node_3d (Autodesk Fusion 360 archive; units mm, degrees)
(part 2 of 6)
sketch "mountbottom" plane through (0, 0, -26) normal (0, 0, 1) x axis (-1, 0, 0)
  line L1 (-3.25, -49) -> (-15, -49)
  line L2 (-3.25, -50.9) -> (-3.25, -49)
  line L3 (3.25, -50.9) -> (-3.25, -50.9)
  line L4 (3.25, -49) -> (3.25, -50.9)
  line L5 (15, -49) -> (3.25, -49)
  line L6 (15, -47) -> (15, -49)
  line L7 (46, -47) -> (15, -47)
  line L8 (47, 46) -> (47, -46)
  line L9 (-46, 47) -> (46, 47)
  line L10 (-47, -46) -> (-47, 46)
  line L11 (-15, -47) -> (-46, -47)
  line L12 (-15, -49) -> (-15, -47)
  line L13 (-15.575, -12.63) -> (-15.575, 11.37)
  line L14 (12.425, -16.63) -> (-11.575, -16.63)
  line L15 (16.425, 11.37) -> (16.425, -12.63)
  line L16 (-11.575, 15.37) -> (12.425, 15.37)
  line L17 (4.235, 0.64) -> (-3.385, 0.64)
  line L18 (4.235, -1.9) -> (4.235, 0.64)
  line L19 (-3.385, -1.9) -> (4.235, -1.9)
  line L20 (-3.385, 0.64) -> (-3.385, -1.9)
  line L21 (-2.715, -0.03) -> (-1.515, -0.03)
  line L22 (-2.715, -1.23) -> (-2.715, -0.03)
  line L23 (-1.515, -1.23) -> (-2.715, -1.23)
  line L24 (-1.515, -0.03) -> (-1.515, -1.23)
  line L25 (-0.175, -0.03) -> (1.025, -0.03)
  line L26 (-0.175, -1.23) -> (-0.175, -0.03)
  line L27 (1.025, -1.23) -> (-0.175, -1.23)
  line L28 (1.025, -0.03) -> (1.025, -1.23)
  line L29 (2.365, -0.03) -> (3.565, -0.03)
  line L30 (2.365, -1.23) -> (2.365, -0.03)
  line L31 (3.565, -1.23) -> (2.365, -1.23)
  line L32 (3.565, -0.03) -> (3.565, -1.23)
  line L33 (4.035, 1.44) -> (-3.185, 1.44)
  line L34 (5.035, -1.7) -> (5.035, 0.44)
  line L35 (-3.185, -2.7) -> (4.035, -2.7)
  line L36 (-4.185, 0.44) -> (-4.185, -1.7)
  line L37 (8.425, 7.37) -> (16.425, 15.37)
  line L38 (16.425, 7.37) -> (8.425, 15.37)
  line L39 (11.375, 14.92) -> (13.475, 14.92)
  line L40 (8.875, 10.32) -> (8.875, 12.42)
  line L41 (13.475, 7.82) -> (11.375, 7.82)
  line L42 (15.975, 12.42) -> (15.975, 10.32)
  line L43 (8.875, 7.82) -> (15.975, 14.92)
  line L44 (15.975, 7.82) -> (8.875, 14.92)
  line L45 (-10.525, 7.82) -> (-12.625, 7.82)
  line L46 (-8.025, 12.42) -> (-8.025, 10.32)
  line L47 (-12.625, 14.92) -> (-10.525, 14.92)
  line L48 (-15.125, 10.32) -> (-15.125, 12.42)
  line L49 (-8.025, 14.92) -> (-15.125, 7.82)
  line L50 (-15.125, 14.92) -> (-8.025, 7.82)
  line L51 (11.375, -9.08) -> (13.475, -9.08)
  line L52 (8.875, -13.68) -> (8.875, -11.58)
  line L53 (13.475, -16.18) -> (11.375, -16.18)
  line L54 (15.975, -11.58) -> (15.975, -13.68)
  line L55 (8.875, -16.18) -> (15.975, -9.08)
  line L56 (15.975, -16.18) -> (8.875, -9.08)
  line L57 (-12.625, -9.08) -> (-10.525, -9.08)
  line L58 (-15.125, -13.68) -> (-15.125, -11.58)
  line L59 (-10.525, -16.18) -> (-12.625, -16.18)
  line L60 (-8.025, -11.58) -> (-8.025, -13.68)
  line L61 (-15.125, -16.18) -> (-8.025, -9.08)
  line L62 (-8.025, -16.18) -> (-15.125, -9.08)
  arc A1 centre (46, -46) radius 1 clockwise from (47, -46) to (46, -47)
  arc A2 centre (46, 46) radius 1 clockwise from (46, 47) to (47, 46)
  arc A3 centre (-46, 46) radius 1 clockwise from (-47, 46) to (-46, 47)
  arc A4 centre (-46, -46) radius 1 clockwise from (-46, -47) to (-47, -46)
  arc A5 centre (-11.575, 11.37) radius 4 clockwise from (-15.575, 11.37) to (-11.575, 15.37)
  arc A6 centre (-11.575, -12.63) radius 4 clockwise from (-11.575, -16.63) to (-15.575, -12.63)
  arc A7 centre (12.425, -12.63) radius 4 clockwise from (16.425, -12.63) to (12.425, -16.63)
  arc A8 centre (12.425, 11.37) radius 4 clockwise from (12.425, 15.37) to (16.425, 11.37)
  circle C1 centre (12.425, -12.63) radius 1.55
  circle C2 centre (-11.575, -12.63) radius 1.55
  circle C3 centre (12.425, 11.37) radius 1.55
  circle C4 centre (-11.575, 11.37) radius 1.55
  circle C5 centre (16.68, 32.54) radius 4.65
  circle C6 centre (-16.34, 32.54) radius 1.65
  circle C7 centre (-16.34, 32.54) radius 1.65
  circle C8 centre (-16.34, 32.54) radius 4.65
  circle C9 centre (-16.34, 32.54) radius 4.65
  circle C10 centre (16.68, -32.865) radius 4.65
  circle C11 centre (16.68, -32.865) radius 1.65
  circle C12 centre (-16.33, -33.5) radius 4.65
  circle C13 centre (-16.33, -33.5) radius 1.65
  circle C14 centre (12.425, -12.63) radius 3.55
  circle C15 centre (-11.575, -12.63) radius 3.55
  circle C16 centre (-11.575, 11.37) radius 3.55
  circle C17 centre (12.425, 11.37) radius 3.55
  arc A9 centre (4.035, -1.7) radius 1 clockwise from (5.035, -1.7) to (4.035, -2.7)
  arc A10 centre (4.035, 0.44) radius 1 clockwise from (4.035, 1.44) to (5.035, 0.44)
  arc A11 centre (-3.185, 0.44) radius 1 clockwise from (-4.185, 0.44) to (-3.185, 1.44)
  arc A12 centre (-3.185, -1.7) radius 1 clockwise from (-3.185, -2.7) to (-4.185, -1.7)
  arc A13 centre (13.475, 12.42) radius 2.5 clockwise from (13.475, 14.92) to (15.975, 12.42)
  arc A14 centre (11.375, 12.42) radius 2.5 clockwise from (8.875, 12.42) to (11.375, 14.92)
  arc A15 centre (13.475, 10.32) radius 2.5 clockwise from (15.975, 10.32) to (13.475, 7.82)
  arc A16 centre (11.375, 10.32) radius 2.5 clockwise from (11.375, 7.82) to (8.875, 10.32)
  arc A17 centre (-12.625, 12.42) radius 2.5 clockwise from (-15.125, 12.42) to (-12.625, 14.92)
  arc A18 centre (-10.525, 12.42) radius 2.5 clockwise from (-10.525, 14.92) to (-8.025, 12.42)
  arc A19 centre (-10.525, 10.32) radius 2.5 clockwise from (-8.025, 10.32) to (-10.525, 7.82)
  arc A20 centre (-12.625, 10.32) radius 2.5 clockwise from (-12.625, 7.82) to (-15.125, 10.32)
  arc A21 centre (13.475, -13.68) radius 2.5 clockwise from (15.975, -13.68) to (13.475, -16.18)
  arc A22 centre (11.375, -13.68) radius 2.5 clockwise from (11.375, -16.18) to (8.875, -13.68)
  arc A23 centre (11.375, -11.58) radius 2.5 clockwise from (8.875, -11.58) to (11.375, -9.08)
  arc A24 centre (13.475, -11.58) radius 2.5 clockwise from (13.475, -9.08) to (15.975, -11.58)
  arc A25 centre (-12.625, -13.68) radius 2.5 clockwise from (-12.625, -16.18) to (-15.125, -13.68)
  arc A26 centre (-12.625, -11.58) radius 2.5 clockwise from (-15.125, -11.58) to (-12.625, -9.08)
  arc A27 centre (-10.525, -11.58) radius 2.5 clockwise from (-10.525, -9.08) to (-8.025, -11.58)
  arc A28 centre (-10.525, -13.68) radius 2.5 clockwise from (-8.025, -13.68) to (-10.525, -16.18)
  point P82 (12.425, 11.37)
  point P33 (12.425, 11.37)
  point P87 (12.425, 11.37)
  point P36 (12.425, 11.37)
  point P83 (15.975, 14.92)
  point P84 (8.875, 14.92)
  point P86 (15.975, 7.82)
  point P85 (8.875, 7.82)
  point P104 (-11.575, 11.37)
  point P37 (-11.575, 11.37)
  point P103 (-15.125, 14.92)
  point P102 (-8.025, 14.92)
  point P101 (-8.025, 7.82)
  point P100 (-15.125, 7.82)
  point P121 (12.425, -12.63)
  point P30 (12.425, -12.63)
  point P120 (15.975, -16.18)
  point P119 (8.875, -16.18)
  point P118 (8.875, -9.08)
  point P117 (15.975, -9.08)
  point P138 (-11.575, -12.63)
  point P35 (-11.575, -12.63)
  point P136 (-15.125, -16.18)
  point P135 (-15.125, -9.08)
  point P134 (-8.025, -9.08)
  point P137 (-8.025, -16.18)
  tangent L35 A9
  tangent L34 A9
  tangent L33 A10
  tangent L34 A10
  equal A9 A10
  tangent L33 A11
  tangent L36 A11
  equal A9 A11
  tangent L35 A12
  tangent L36 A12
  equal A9 A12
  coincident L37 P82
  coincident L38 P82
  coincident P33 P82
  horizontal L39
  perpendicular L39 L40
  parallel L39 L41
  parallel L40 L42
  coincident L43 P87
  coincident L44 P87
  coincident P36 P87
  coincident P83 L42
  coincident P83 L39
  tangent L42 A13
  tangent L39 A13
  coincident P84 L39
  coincident P84 L40
  tangent L39 A14
  tangent L40 A14
  equal A13 A14
  coincident P86 L41
  coincident P86 L42
  tangent L41 A15
  tangent L42 A15
  equal A13 A15
  coincident P85 L41
  coincident P85 L40
  tangent L41 A16
  tangent L40 A16
  equal A13 A16
  horizontal L45
  perpendicular L45 L46
  parallel L45 L47
  parallel L46 L48
  coincident L49 P104
  coincident L50 P104
  coincident P37 P104
  coincident P103 L47
  coincident P103 L48
  tangent L47 A17
  tangent L48 A17
  coincident P102 L47
  coincident P102 L46
  tangent L47 A18
  tangent L46 A18
  equal A17 A18
  coincident P101 L46
  coincident P101 L45
  tangent L46 A19
  tangent L45 A19
  equal A17 A19
  coincident P100 L45
  coincident P100 L48
  tangent L45 A20
  tangent L48 A20
  equal A17 A20
  horizontal L51
  perpendicular L51 L52
  parallel L51 L53
  parallel L52 L54
  coincident L55 P121
  coincident L56 P121
  coincident P30 P121
  coincident P120 L53
  coincident P120 L54
  tangent L53 A21
  tangent L54 A21
  coincident P119 L53
  coincident P119 L52
  tangent L53 A22
  tangent L52 A22
  equal A21 A22
  coincident P118 L52
  coincident P118 L51
  tangent L52 A23
  tangent L51 A23
  equal A21 A23
  coincident P117 L51
  coincident P117 L54
  tangent L51 A24
  tangent L54 A24
  equal A21 A24
  horizontal L57
  perpendicular L57 L58
  parallel L57 L59
  parallel L58 L60
  coincident L61 P138
  coincident L62 P138
  coincident P35 P138
  coincident P136 L59
  coincident P136 L58
  tangent L59 A25
  tangent L58 A25
  coincident P135 L58
  coincident P135 L57
  tangent L58 A26
  tangent L57 A26
  equal A25 A26
  coincident P134 L57
  coincident P134 L60
  tangent L57 A27
  tangent L60 A27
  equal A25 A27
  coincident P137 L60
  coincident P137 L59
  tangent L60 A28
  tangent L59 A28
  equal A25 A28
  dimension "d179" = 2
  dimension "d180" = 2
  dimension "d181" = 2
  dimension "d182" = 2
  dimension "d186" radius A9 = 1
  dimension "d331" distance P85 P86 = 7.1
  dimension "d332" distance P84 P85 = 7.1
  dimension "d333" radius A13 = 2.5
  dimension "d336" distance P102 P103 = 7.1
  dimension "d337" distance P101 P102 = 7.1
  dimension "d338" radius A17 = 2.5
  dimension "d339" distance P119 P120 = 7.1
  dimension "d340" distance P118 P119 = 7.1
  dimension "d341" radius A21 = 2.5
  dimension "d342" distance P136 P137 = 7.1
  dimension "d343" distance P135 P136 = 7.1
  dimension "d344" radius A25 = 2.5
extrude "Extrude25" new body sketch "mountbottom" profile of C1 C2 C3 C4 C14 C15 C16 C17 to an object bodies "dwnmount4", "dwnmount2", "dwnmount1", "dwnmount4 (1)"
extrude "Extrude26" cut sketch "mountbottom" profile of L17 L18 L19 L20 L21 L22 L23 L24 L25 L26 L27 L28 L29 L30 L31 L32 L34 L33 L35 L36 A9 A10 A11 A12 against normal blind 9
offset_faces "OffsetFaces12" distance 0.2
offset_faces "OffsetFaces13" distance 0.2
move "Move1" TranslateX 0 TranslateY 0 TranslateZ 0.2
sketch "Sketch16" plane through (0, 0, -5.4) normal (0, 0, 1) x axis (-1, 0, 0)
  line L1 (51.5, 45) -> (51.5, -45)
  line L2 (-47.5, 49) -> (47.5, 49)
  line L3 (-51.5, -45) -> (-51.5, 45)
  line L4 (47.5, -49) -> (-47.5, -49)
  line L5 (-14.78, -33.5) -> (-16.33, -33.5)
  line L6 (-21, -32.865) -> (16.68, -32.865)
  line L7 (-16.34, 32.54) -> (16.68, 32.54)
  line L8 (-12.83, -29.5) -> (-19.83, -37.5)
  line L9 (-19.83, -29.5) -> (-12.83, -37.5)
  line L10 (-16, -20) -> (-16, -48)
  line L11 (-18, -48) -> (-18, -20)
  line L12 (-16, -32.865) -> (-18, -32.865)
  line L13 (-20.5, -28.865) -> (-13.5, -36.865)
  line L14 (-13.5, -28.865) -> (-20.5, -36.865)
  line L15 (-16.8856, -34.6) -> (-16.8856, -32.865)
  line L16 (-20.3856, -36.865) -> (-13.3856, -28.865)
  line L17 (-13.3856, -36.865) -> (-20.3856, -28.865)
  line L18 (-18.3856, -36.865) -> (-15.3856, -36.865)
  line L19 (-20.3856, -30.865) -> (-20.3856, -34.865)
  line L20 (-15.3856, -28.865) -> (-18.3856, -28.865)
  line L21 (-13.3856, -34.865) -> (-13.3856, -30.865)
  line L22 (-20.3856, -28.865) -> (-13.3856, -36.865)
  line L23 (-13.3856, -28.865) -> (-20.3856, -36.865)
  line L24 (-18, 20) -> (-18, 48)
  line L25 (-16, 48) -> (-16, 20)
  line L26 (16, 20) -> (16, 48)
  line L27 (18, 48) -> (18, 20)
  line L28 (18, -20) -> (18, -48)
  line L29 (16, -48) -> (16, -20)
  line L30 (18, -32.865) -> (16, -32.865)
  line L31 (17, -34.3816) -> (17, -32.865)
  line L32 (13.18, -32.865) -> (20.18, -32.865)
  line L33 (15.5, -36.865) -> (18.5, -36.865)
  line L34 (13.5, -30.865) -> (13.5, -34.865)
  line L35 (18.5, -28.865) -> (15.5, -28.865)
  line L36 (20.5, -34.865) -> (20.5, -30.865)
  line L37 (13.5, -28.865) -> (20.5, -36.865)
  line L38 (20.5, -28.865) -> (13.5, -36.865)
  line L39 (-18, 32.54) -> (-16, 32.54)
  line L40 (-17, 30.5) -> (-17, 32.54)
  line L41 (-18.5, 28.54) -> (-15.5, 28.54)
  line L42 (-20.5, 34.54) -> (-20.5, 30.54)
  line L43 (-15.5, 36.54) -> (-18.5, 36.54)
  line L44 (-13.5, 30.54) -> (-13.5, 34.54)
  line L45 (-20.5, 36.54) -> (-13.5, 28.54)
  line L46 (-13.5, 36.54) -> (-20.5, 28.54)
  line L47 (18, 32.54) -> (16, 32.54)
  line L48 (17, 28) -> (17, 32.54)
  line L49 (15.5, 28.54) -> (18.5, 28.54)
  line L50 (13.5, 34.54) -> (13.5, 30.54)
  line L51 (18.5, 36.54) -> (15.5, 36.54)
  line L52 (20.5, 30.54) -> (20.5, 34.54)
  line L53 (13.5, 36.54) -> (20.5, 28.54)
  line L54 (20.5, 36.54) -> (13.5, 28.54)
  arc A1 centre (47.5, -45) radius 4 clockwise from (51.5, -45) to (47.5, -49)
  arc A2 centre (47.5, 45) radius 4 clockwise from (47.5, 49) to (51.5, 45)
  arc A3 centre (-47.5, 45) radius 4 clockwise from (-51.5, 45) to (-47.5, 49)
  arc A4 centre (-47.5, -45) radius 4 clockwise from (-47.5, -49) to (-51.5, -45)
  circle C1 centre (-36.64, 35.04) radius 0.7747
  circle C2 centre (-30.29, 37.58) radius 0.7747
  circle C3 centre (-37.91, 32.5) radius 0.8763
  circle C4 centre (-32.83, 32.5) radius 2.0447
  circle C5 centre (-27.75, 32.5) radius 0.8763
  circle C6 centre (-16.34, 32.54) radius 1.55
  circle C7 centre (-3.64, 35.04) radius 0.7747
  circle C8 centre (-4.91, 32.5) radius 0.8763
  circle C9 centre (-36.64, 2.04) radius 0.7747
  circle C10 centre (-30.29, 4.58) radius 0.7747
  circle C11 centre (-3.64, 2.04) radius 0.7747
  circle C12 centre (2.71, 37.58) radius 0.7747
  circle C13 centre (0.17, 32.5) radius 2.0447
  circle C14 centre (5.25, 32.5) radius 0.8763
  circle C15 centre (16.68, 32.54) radius 1.55
  circle C16 centre (29.36, 35.04) radius 0.7747
  circle C17 centre (28.09, 32.5) radius 0.8763
  circle C18 centre (35.71, 37.58) radius 0.7747
  circle C19 centre (33.17, 32.5) radius 2.0447
  circle C20 centre (38.25, 32.5) radius 0.8763
  circle C21 centre (2.71, 4.58) radius 0.7747
  circle C22 centre (29.36, 2.04) radius 0.7747
  circle C23 centre (35.71, 4.58) radius 0.7747
  circle C24 centre (-37.91, -0.5) radius 0.8763
  circle C25 centre (-32.83, -0.5) radius 2.0447
  circle C26 centre (-27.75, -0.5) radius 0.8763
  circle C27 centre (-4.91, -0.5) radius 0.8763
  circle C28 centre (-30.29, -28.42) radius 0.7747
  circle C29 centre (-36.64, -30.96) radius 0.7747
  circle C30 centre (-37.91, -33.5) radius 0.8763
  circle C31 centre (-32.83, -33.5) radius 2.0447
  circle C32 centre (-27.75, -33.5) radius 0.8763
  circle C33 centre (-16.33, -33.5) radius 1.55
  circle C34 centre (-4.91, -33.5) radius 0.8763
  circle C35 centre (-3.64, -30.96) radius 0.7747
  circle C36 centre (0.17, -0.5) radius 2.0447
  circle C37 centre (5.25, -0.5) radius 0.8763
  circle C38 centre (28.09, -0.5) radius 0.8763
  circle C39 centre (33.17, -0.5) radius 2.0447
  circle C40 centre (38.25, -0.5) radius 0.8763
  circle C41 centre (2.71, -28.42) radius 0.7747
  circle C42 centre (0.17, -33.5) radius 2.0447
  circle C43 centre (5.25, -33.5) radius 0.8763
  circle C44 centre (16.68, -32.865) radius 1.55
  circle C45 centre (29.36, -30.96) radius 0.7747
  circle C46 centre (28.09, -33.5) radius 0.8763
  circle C47 centre (35.71, -28.42) radius 0.7747
  circle C48 centre (33.17, -33.5) radius 2.0447
  circle C49 centre (38.25, -33.5) radius 0.8763
  circle C50 centre (16.68, -32.865) radius 2.675
  circle C51 centre (-16.33, -33.5) radius 2.675
  circle C52 centre (16.68, 32.54) radius 2.675
  circle C53 centre (-16.34, 32.54) radius 2.675
  arc A5 centre (-18.3856, -30.865) radius 2 clockwise from (-20.3856, -30.865) to (-18.3856, -28.865)
  arc A6 centre (-15.3856, -30.865) radius 2 clockwise from (-15.3856, -28.865) to (-13.3856, -30.865)
  arc A7 centre (-15.3856, -34.865) radius 2 clockwise from (-13.3856, -34.865) to (-15.3856, -36.865)
  arc A8 centre (-18.3856, -34.865) radius 2 clockwise from (-18.3856, -36.865) to (-20.3856, -34.865)
  arc A9 centre (15.5, -30.865) radius 2 clockwise from (13.5, -30.865) to (15.5, -28.865)
  arc A10 centre (18.5, -30.865) radius 2 clockwise from (18.5, -28.865) to (20.5, -30.865)
  arc A11 centre (18.5, -34.865) radius 2 clockwise from (20.5, -34.865) to (18.5, -36.865)
  arc A12 centre (15.5, -34.865) radius 2 clockwise from (15.5, -36.865) to (13.5, -34.865)
  arc A13 centre (-18.5, 34.54) radius 2 clockwise from (-20.5, 34.54) to (-18.5, 36.54)
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  point P64 (-16.33, -33.5)
  point P67 (-16.33, -33.5)
  point P68 (-14.78, -33.5)
  point P63 (16.68, -32.865)
  point P69 (16.68, -32.865)
  point P28 (16.68, 32.54)
  point P71 (16.68, 32.54)
  point P66 (-16.34, 32.54)
  point P72 (-16.34, 32.54)
  point P73 (16.68, 32.54)
  point P74 (-16.34, 32.54)
  point P75 (16.68, -32.865)
  point P80 (-16.33, -33.5)
  point P85 (-18, -32.865)
  point P86 (-16, -32.865)
  point P91 (-17, -32.865)
  point P92 (-16.8856, -32.865)
  point P98 (-16.8856, -32.865)
  point P103 (-16.8856, -32.865)
  point P101 (-20.3856, -28.865)
  point P102 (-13.3856, -28.865)
  point P99 (-13.3856, -36.865)
  point P100 (-20.3856, -36.865)
  point P128 (16, -32.865)
  point P129 (18, -32.865)
  point P130 (17, -32.865)
  point P131 (17, -34.3816)
  point P138 (17, -32.865)
  point P136 (13.5, -28.865)
  point P137 (20.5, -28.865)
  point P134 (20.5, -36.865)
  point P135 (13.5, -36.865)
  point P151 (-16, 32.54)
  point P152 (-18, 32.54)
  point P153 (-17, 32.54)
  point P159 (-17, 32.54)
  point P157 (-20.5, 36.54)
  point P158 (-13.5, 36.54)
  point P155 (-13.5, 28.54)
  point P156 (-20.5, 28.54)
  point P172 (16, 32.54)
  point P173 (18, 32.54)
  point P174 (17, 32.54)
  point P180 (17, 32.54)
  point P178 (13.5, 36.54)
  point P177 (13.5, 28.54)
  point P176 (20.5, 28.54)
  point P179 (20.5, 36.54)
  point P78 (-12.83, -29.5)
  point P79 (-19.83, -29.5)
  point P77 (-12.83, -37.5)
  point P89 (-20.5, -28.865)
  point P90 (-13.5, -28.865)
  point P88 (-20.5, -36.865)
  point P96 (-20.3856, -36.865)
  point P97 (-13.3856, -36.865)
  point P95 (-20.3856, -28.865)
  concentric C44 C50
  concentric C33 C51
  concentric C15 C52
  concentric C6 C53
  coincident P64 P67
  coincident C33 P68
  horizontal L5
  coincident P63 P69
  horizontal L6
  coincident P28 P71
  coincident P66 P72
  coincident P71 P73
  coincident P66 P74
  coincident P63 P75
  coincident L8 P80
  coincident L9 P80
  coincident P64 P80
  coincident L11 P85
  coincident L6 P85
  coincident L10 P86
  coincident L6 P86
  coincident L13 P91
  coincident L14 P91
  coincident L12 P92
  coincident L9 P92
  perpendicular L12 L15
  coincident L16 P98
  coincident L17 P98
  coincident P92 P98
  horizontal L18
  perpendicular L18 L19
  parallel L18 L20
  parallel L19 L21
  coincident L22 P103
  coincident L23 P103
  coincident P92 P103
  coincident P101 L19
  coincident P101 L20
  tangent L19 A5
  tangent L20 A5
  coincident P102 L20
  coincident P102 L21
  tangent L20 A6
  tangent L21 A6
  equal A5 A6
  coincident P99 L21
  coincident P99 L18
  tangent L21 A7
  tangent L18 A7
  equal A5 A7
  coincident P100 L18
  coincident P100 L19
  tangent L18 A8
  tangent L19 A8
  equal A5 A8
  coincident L6 P128
  coincident L29 P128
  coincident L28 P129
  perpendicular L28 L30
  midpoint L30 P130
  coincident C44 P131
  perpendicular L30 L31
  horizontal L33
  perpendicular L33 L34
  parallel L33 L35
  parallel L34 L36
  coincident L37 P138
  coincident L38 P138
  coincident P130 P138
  coincident P136 L35
  coincident P136 L34
  tangent L35 A9
  tangent L34 A9
  coincident P137 L35
  coincident P137 L36
  tangent L35 A10
  tangent L36 A10
  equal A9 A10
  coincident P134 L36
  coincident P134 L33
  tangent L36 A11
  tangent L33 A11
  equal A9 A11
  coincident P135 L34
  coincident P135 L33
  tangent L34 A12
  tangent L33 A12
  coincident L25 P151
  coincident L7 P151
  coincident L24 P152
  perpendicular L24 L39
  midpoint L39 P153
  perpendicular L39 L40
  horizontal L41
  perpendicular L41 L42
  parallel L41 L43
  parallel L42 L44
  coincident L45 P159
  coincident L46 P159
  coincident P153 P159
  coincident P157 L42
  coincident P157 L43
  tangent L42 A13
  tangent L43 A13
  coincident P158 L43
  coincident P158 L44
  coincident P155 L44
  coincident P155 L41
  coincident P156 L41
  coincident P156 L42
  coincident L26 P172
  coincident L7 P172
  coincident L27 P173
  perpendicular L27 L47
  midpoint L47 P174
  perpendicular L47 L48
  horizontal L49
  perpendicular L49 L50
  parallel L49 L51
  parallel L50 L52
  coincident L53 P180
  coincident L54 P180
  coincident P174 P180
  coincident P178 L51
  coincident P178 L50
  coincident P177 L50
  coincident P177 L49
  coincident P176 L49
  coincident P176 L52
  coincident P179 L52
  coincident P179 L51
  dimension "d194" diameter C50 = 5.35
  dimension "d195" diameter C51 = 5.35
  dimension "d196" diameter C52 = 5.35
  dimension "d197" diameter C53 = 5.35
  dimension "d222" distance P78 P79 = 7
  dimension "d223" distance P77 P78 = 8
  dimension "d229" distance P89 P90 = 7
  dimension "d230" distance P88 P89 = 8
  dimension "d231" distance P96 P97 = 7
  dimension "d232" distance P95 P96 = 8
  dimension "d233" distance P101 P102 = 7
  dimension "d234" distance P100 P101 = 8
  dimension "d235" radius A5 = 2
  dimension "d237" distance P136 P137 = 7
  dimension "d238" distance P135 P136 = 8
  dimension "d239" radius A9 = 2
  dimension "d240" radius A12 = 2
  dimension "d241" distance P157 P158 = 7
  dimension "d242" radius A13 = 2
  dimension "d243" distance P178 P179 = 7
  dimension "d244" distance P177 P178 = 8
  dimension "d245" radius = 2
  dimension "d246" radius = 2
extrude "Extrude27" new body sketch "keyplate" profile of L1 L2 L3 L4 L7 L8 L9 L10 A1 A2 A3 A4 L13 L14 L15 L16 L17 L18 L19 L20 L21 L22 L23 L24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 to an object
move "Move1" TranslateX 0 TranslateY 0 TranslateZ 0.8
position "Position3"
circular_pattern "C-Pattern1" TotalAngle 360
circular_pattern "C-Pattern2" TotalAngle 360
extrude "Extrude29" new body sketch "Sketch16" along normal blind 3.8
extrude "Extrude31" cut sketch "Sketch16" profile of C6 C15 C33 C44 C50 C51 C52 C53 L10 L11 L12 L24 L25 L26 L27 L28 L29 L32 L39 L40 along normal blind 3.5
extrude "Extrude32" sketch "close" profile of L9 L10 L11 L12 A1 A2 A3 A4 blind 1.5
fillet "Fillet4" radius 1.75
circular_pattern "C-Pattern4" TotalAngle 360 bodies "close (1)", "close (2)", "close (3)"
circular_pattern "C-Pattern5" TotalAngle 360
circular_pattern "C-Pattern6" TotalAngle 360
sketch "Sketch17" plane through (0, 0, -26) normal (0, 0, 1) x axis (-1, 0, 0)
  line L1 (-4.185, 0.44) -> (-4.185, -1.7)
  line L2 (4.035, 1.44) -> (-3.185, 1.44)
  line L3 (5.035, -1.7) -> (5.035, 0.44)
  line L4 (-3.185, -2.7) -> (4.035, -2.7)
  line L5 (-49, 3.25) -> (-49, 15)
  line L6 (-50.9, 3.25) -> (-49, 3.25)
  line L7 (-50.9, -3.25) -> (-50.9, 3.25)
  line L8 (-49, -3.25) -> (-50.9, -3.25)
  line L9 (-49, -15) -> (-49, -3.25)
  line L10 (-47, -15) -> (-49, -15)
  line L11 (-47, -46) -> (-47, -15)
  line L12 (-15, -47) -> (-46, -47)
  line L13 (-15, -49) -> (-15, -47)
  line L14 (-3.25, -49) -> (-15, -49)
  line L15 (-3.25, -50.9) -> (-3.25, -49)
  line L16 (3.25, -50.9) -> (-3.25, -50.9)
  line L17 (3.25, -49) -> (3.25, -50.9)
  line L18 (15, -49) -> (3.25, -49)
  line L19 (15, -47) -> (15, -49)
  line L20 (46, -47) -> (15, -47)
  line L21 (47, -15) -> (47, -46)
  line L22 (49, -15) -> (47, -15)
  line L23 (49, -3.25) -> (49, -15)
  line L24 (50.9, -3.25) -> (49, -3.25)
  line L25 (50.9, 3.25) -> (50.9, -3.25)
  line L26 (49, 3.25) -> (50.9, 3.25)
  line L27 (49, 15) -> (49, 3.25)
  line L28 (47, 15) -> (49, 15)
  line L29 (47, 46) -> (47, 15)
  line L30 (15, 47) -> (46, 47)
  line L31 (15, 49) -> (15, 47)
  line L32 (3.25, 49) -> (15, 49)
  line L33 (3.25, 50.9) -> (3.25, 49)
  line L34 (-3.25, 50.9) -> (3.25, 50.9)
  line L35 (-3.25, 49) -> (-3.25, 50.9)
  line L36 (-15, 49) -> (-3.25, 49)
  line L37 (-15, 47) -> (-15, 49)
  line L38 (-46, 47) -> (-15, 47)
  line L39 (-47, 15) -> (-47, 46)
  line L40 (-49, 15) -> (-47, 15)
  line L41 (14.85, -49.15) -> (14.85, -46.8)
  line L42 (19.85, -49.15) -> (14.85, -49.15)
  line L43 (19.85, -50.9) -> (19.85, -49.15)
  line L44 (3.25, -50.9) -> (19.85, -50.9)
  line L45 (3.25, -46.8) -> (3.25, -50.9)
  line L46 (14.85, -46.8) -> (3.25, -46.8)
  line L47 (-14.85, -46.8) -> (-14.85, -49.15)
  line L48 (-3.25, -46.8) -> (-14.85, -46.8)
  line L49 (-3.25, -50.9) -> (-3.25, -46.8)
  line L50 (-19.85, -50.9) -> (-3.25, -50.9)
  line L51 (-19.85, -49.15) -> (-19.85, -50.9)
  line L52 (-14.85, -49.15) -> (-19.85, -49.15)
  line L53 (-14.85, -49.15) -> (14.85, -49.15)
  line L54 (-14.85, -49.15) -> (14.85, -49.15)
  line L55 (-14.85, -50.9) -> (-14.85, -49.15)
  line L56 (14.85, -50.9) -> (14.85, -49.15)
  arc A1 centre (-3.185, 0.44) radius 1 clockwise from (-4.185, 0.44) to (-3.185, 1.44)
  arc A2 centre (4.035, 0.44) radius 1 clockwise from (4.035, 1.44) to (5.035, 0.44)
  arc A3 centre (4.035, -1.7) radius 1 clockwise from (5.035, -1.7) to (4.035, -2.7)
  arc A4 centre (-3.185, -1.7) radius 1 clockwise from (-3.185, -2.7) to (-4.185, -1.7)
  arc A5 centre (-46, -46) radius 1 clockwise from (-46, -47) to (-47, -46)
  arc A6 centre (46, -46) radius 1 clockwise from (47, -46) to (46, -47)
  arc A7 centre (46, 46) radius 1 clockwise from (46, 47) to (47, 46)
  arc A8 centre (-46, 46) radius 1 clockwise from (-47, 46) to (-46, 47)
  point P59 (14.85, -49.15)
  point P70 (14.85, -49.15)
  point P64 (-14.85, -49.15)
  point P71 (-14.85, -49.15)
  point P72 (14.85, -49.15)
  point P73 (-14.85, -50.9)
  point P74 (14.85, -50.9)
  coincident P59 P70
  coincident P64 P71
  coincident P59 P72
  coincident L50 P73
  perpendicular L50 L55
  coincident L44 P74
  perpendicular L44 L56
extrude "Extrude34" sketch "keyplate" profile of L65 L69 L70 L71 L72 L73 L74 L75 L76 L77 L104 L105 to an object
rectangular_pattern "R-Pattern1" uSpaceDistance 68 vSpaceDistance -34
extrude "Extrude35" sketch "mounts" profile of C1 C2 C3 C4 C9 C10 C11 C12 blind 3.5
component_insert "Component Insert6"
joint "Assemble2" alignAngle 0 alignOffsetX 0 alignOffsetY 0 alignOffsetZ 0
offset_faces "OffsetFaces16" distance -3
offset_faces "OffsetFaces17" distance -3
offset_faces "OffsetFaces18" distance -3
offset_faces "OffsetFaces19" distance -3
offset_faces "OffsetFaces20" distance 2.85
offset_faces "OffsetFaces21" distance 2.85
offset_faces "OffsetFaces22" distance 2.85
offset_faces "OffsetFaces23" distance 2.85
sketch "Sketch18" plane through (0, 0, -6.8) normal (0, 0, 1) x axis (-1, 0, 0)
  circle C1 centre (16.68, -32.865) radius 1.65
  circle C2 centre (16.68, -32.865) radius 4.65
  circle C3 centre (16.68, -32.865) radius 2.75
  circle C4 centre (-16.33, -33.5) radius 1.65
  circle C5 centre (-16.33, -33.5) radius 4.65
  circle C6 centre (-16.34, 32.54) radius 1.65
  circle C7 centre (-16.34, 32.54) radius 4.65
  circle C8 centre (16.68, 32.54) radius 1.65
  circle C9 centre (16.68, 32.54) radius 4.65
  circle C10 centre (-16.33, -33.5) radius 2.75
  circle C11 centre (16.68, 32.54) radius 2.75
  circle C12 centre (-16.34, 32.54) radius 2.75
  concentric C1 C3
  concentric C4 C10
  concentric C8 C11
  concentric C6 C12
  dimension "d294" diameter C3 = 5.5
  dimension "d297" diameter C10 = 5.5
  dimension "d298" diameter C11 = 5.5
  dimension "d299" diameter C12 = 5.5
extrude "Extrude36" cut sketch "Sketch18" profile of C1 C3 against normal blind 29
extrude "Extrude37" cut sketch "Sketch18" profile of C4 C6 C8 C10 C11 C12 against normal blind 50
fillet "Fillet5" radius 1.25
fillet "Fillet6" radius 1.25
extrude "Extrude38" add sketch "mounts" profile of C5 L25 L26 L27 L28 A13 A14 A15 A16 to an object bodies "upmount1"
extrude "Extrude39" add sketch "mounts" profile of C6 L31 L32 L33 L34 A17 A18 A19 A20 to an object bodies "upmount2"
extrude "Extrude40" add sketch "mounts" profile of C7 L13 L14 L15 L16 A5 A6 A7 A8 to an object bodies "upmount4"
extrude "Extrude41" add sketch "mounts" profile of C8 L19 L20 L21 L22 A9 A10 A11 A12 to an object bodies "upmount3"
fillet "Fillet7" radius 1
extrude "Extrude42" add sketch "mountbottom" profile of C17 L39 L40 L41 L42 A13 A14 A15 A16 to an object bodies "dwnmount4"
extrude "Extrude43" add sketch "mountbottom" profile of C14 L51 L52 L53 L54 A21 A22 A23 A24 to an object bodies "dwnmount1"
extrude "Extrude44" add sketch "mountbottom" profile of C15 L57 L58 L59 L60 A25 A26 A27 A28 to an object bodies "dwnmount2"
extrude "Extrude45" add sketch "mountbottom" profile of C16 L45 L46 L47 L48 A17 A18 A19 A20 to an object bodies "dwnmount4 (1)"
mirror "Mirror1" mirrorStitchTolerance 0.1 bodies "pcbholdup (1)"
mirror "Mirror2" mirrorStitchTolerance 0.1 bodies "pcbholdup (2)", "pcbholdup (1) (1)"
move "Move2" TranslateX 0 TranslateY 0 TranslateZ 2.1
fillet "Fillet8" radius 1
sketch "Sketch20" plane through (0, 0, -3.3) normal (0, 0, 1) x axis (-1, 0, 0)
  line L1 (44.2206, -51.997) -> (44.2206, -50)
  line L2 (51.5, -44) -> (52, -44)
  line L3 (51.5, -45) -> (51.5, -44)
  line L4 (45.2206, -49) -> (47.5, -49)
  line L5 (-45, -53) -> (45, -53)
  line L6 (53, -45) -> (53, 45)
  line L7 (44.2206, -53) -> (44.2206, -51.997)
  line L8 (38.2206, -53) -> (44.2206, -53)
  line L9 (38.2206, -51) -> (38.2206, -53)
  line L10 (44.2206, -51) -> (38.2206, -51)
  line L11 (44.2206, -53) -> (44.2206, -51)
  arc A1 centre (45.2206, -50) radius 1 clockwise from (44.2206, -50) to (45.2206, -49)
  arc A2 centre (44, -44) radius 8 clockwise from (52, -44) to (44.2206, -51.997)
  arc A3 centre (47.5, -45) radius 4 clockwise from (51.5, -45) to (47.5, -49)
  arc A4 centre (45, -45) radius 8 clockwise from (53, -45) to (45, -53)
  point P5 (44.2206, -51.997)
  point P17 (44.2206, -51.997)
  point P18 (44.2206, -53)
  point P19 (38.2206, -53)
  point P21 (44.2206, -51)
  coincident P5 P17
  coincident L5 P18
  perpendicular L5 L7
  horizontal L8
  vertical L9
  horizontal L10
  vertical L11
  dimension "d365" distance P18 P19 = 6
  dimension "d366" distance P18 P21 = 2
extrude "Extrude46" new body sketch "Sketch20" profile of L1 L5 L7 L8 L9 L10 L11 to an object bodies "notch (3)"
fillet "Fillet10" radius 0.6
mirror "Mirror3" mirrorStitchTolerance 0.1 bodies "notch (2)"
mirror "Mirror4" mirrorStitchTolerance 0.1 bodies "notch", "notch (1)"
sketch "Sketch21" plane through (0, 0, 2.1) normal (0, 0, 1) x axis (-1, 0, 0)
  line L1 (-20, -50) -> (-18, -48)
  line L2 (-48, -50) -> (-20, -50)
  line L3 (-50, -48) -> (-48, -50)
  line L4 (-50, -20) -> (-50, -48)
  line L5 (-48, -18) -> (-50, -20)
  line L6 (-20, -18) -> (-48, -18)
  line L7 (-18, -20) -> (-20, -18)
  line L8 (-18, -48) -> (-18, -20)
  line L9 (48, -16) -> (50, -14)
  line L10 (20, -16) -> (48, -16)
  line L11 (18, -14) -> (20, -16)
  line L12 (18, 14) -> (18, -14)
  line L13 (20, 16) -> (18, 14)
  line L14 (48, 16) -> (20, 16)
  line L15 (50, 14) -> (48, 16)
  line L16 (50, -14) -> (50, 14)
  line L17 (14, -50) -> (16, -48)
  line L18 (-14, -50) -> (14, -50)
  line L19 (-16, -48) -> (-14, -50)
  line L20 (-16, -20) -> (-16, -48)
  line L21 (-14, -18) -> (-16, -20)
  line L22 (14, -18) -> (-14, -18)
  line L23 (16, -20) -> (14, -18)
  line L24 (16, -48) -> (16, -20)
  line L25 (18, -48) -> (20, -50)
  line L26 (18, -20) -> (18, -48)
  line L27 (20, -18) -> (18, -20)
  line L28 (48, -18) -> (20, -18)
  line L29 (50, -20) -> (48, -18)
  line L30 (50, -48) -> (50, -20)
  line L31 (48, -50) -> (50, -48)
  line L32 (20, -50) -> (48, -50)
  line L33 (-20, -16) -> (-18, -14)
  line L34 (-48, -16) -> (-20, -16)
  line L35 (-50, -14) -> (-48, -16)
  line L36 (-50, 14) -> (-50, -14)
  line L37 (-48, 16) -> (-50, 14)
  line L38 (-20, 16) -> (-48, 16)
  line L39 (-18, 14) -> (-20, 16)
  line L40 (-18, -14) -> (-18, 14)
  line L41 (14, -16) -> (16, -14)
  line L42 (-14, -16) -> (14, -16)
  line L43 (-16, -14) -> (-14, -16)
  line L44 (-16, 14) -> (-16, -14)
  line L45 (-14, 16) -> (-16, 14)
  line L46 (14, 16) -> (-14, 16)
  line L47 (16, 14) -> (14, 16)
  line L48 (16, -14) -> (16, 14)
  line L49 (48, 18) -> (50, 20)
  line L50 (20, 18) -> (48, 18)
  line L51 (18, 20) -> (20, 18)
  line L52 (18, 48) -> (18, 20)
  line L53 (20, 50) -> (18, 48)
  line L54 (48, 50) -> (20, 50)
  line L55 (50, 48) -> (48, 50)
  line L56 (50, 20) -> (50, 48)
  line L57 (14, 18) -> (16, 20)
  line L58 (-14, 18) -> (14, 18)
  line L59 (-16, 20) -> (-14, 18)
  line L60 (-16, 48) -> (-16, 20)
  line L61 (-14, 50) -> (-16, 48)
  line L62 (14, 50) -> (-14, 50)
  line L63 (16, 48) -> (14, 50)
  line L64 (16, 20) -> (16, 48)
  line L65 (-20, 18) -> (-18, 20)
  line L66 (-48, 18) -> (-20, 18)
  line L67 (-50, 20) -> (-48, 18)
  line L68 (-50, 48) -> (-50, 20)
  line L69 (-48, 50) -> (-50, 48)
  line L70 (-20, 50) -> (-48, 50)
  line L71 (-18, 48) -> (-20, 50)
  line L72 (-18, 20) -> (-18, 48)
  line L73 (-52.95, -44.75) -> (-52.95, 44.75)
  line L74 (44.75, -52.95) -> (-44.75, -52.95)
  line L75 (52.95, 44.75) -> (52.95, -44.75)
  line L76 (-44.75, 52.95) -> (44.75, 52.95)
  line L77 (-43.6206, -51) -> (-38.8206, -51)
  line L78 (-44.2206, -53) -> (-44.2206, -51.6)
  line L79 (-38.2206, -53) -> (-44.2206, -53)
  line L80 (-38.2206, -51.6) -> (-38.2206, -53)
  line L81 (38.2206, -53) -> (38.2206, -51.6)
  line L82 (44.2206, -53) -> (38.2206, -53)
  line L83 (44.2206, -51.6) -> (44.2206, -53)
  line L84 (38.8206, -51) -> (43.6206, -51)
  line L85 (-38.2206, -50) -> (-38.2206, -52.95)
  line L86 (38.2206, -50) -> (-38.2206, -50)
  line L87 (38.2206, -52.95) -> (38.2206, -50)
  line L88 (-38.2206, -52.95) -> (38.2206, -52.95)
  line L89 (43.6206, 51) -> (38.8206, 51)
  line L90 (44.2206, 53) -> (44.2206, 51.6)
  line L91 (38.2206, 53) -> (44.2206, 53)
  line L92 (38.2206, 51.6) -> (38.2206, 53)
  line L93 (-38.2206, 53) -> (-38.2206, 51.6)
  line L94 (-44.2206, 53) -> (-38.2206, 53)
  line L95 (-44.2206, 51.6) -> (-44.2206, 53)
  line L96 (-38.8206, 51) -> (-43.6206, 51)
  line L97 (38.2206, 50) -> (38.2206, 52.95)
  line L98 (-38.2206, 50) -> (38.2206, 50)
  line L99 (-38.2206, 52.95) -> (-38.2206, 50)
  line L100 (38.2206, 52.95) -> (-38.2206, 52.95)
  arc A1 centre (-44.75, 44.75) radius 8.2 clockwise from (-52.95, 44.75) to (-44.75, 52.95)
  arc A2 centre (-44.75, -44.75) radius 8.2 clockwise from (-44.75, -52.95) to (-52.95, -44.75)
  arc A3 centre (44.75, -44.75) radius 8.2 clockwise from (52.95, -44.75) to (44.75, -52.95)
  arc A4 centre (44.75, 44.75) radius 8.2 clockwise from (44.75, 52.95) to (52.95, 44.75)
  arc A5 centre (-38.8206, -51.6) radius 0.6 clockwise from (-38.8206, -51) to (-38.2206, -51.6)
  arc A6 centre (-43.6206, -51.6) radius 0.6 clockwise from (-44.2206, -51.6) to (-43.6206, -51)
  arc A7 centre (38.8206, -51.6) radius 0.6 clockwise from (38.2206, -51.6) to (38.8206, -51)
  arc A8 centre (43.6206, -51.6) radius 0.6 clockwise from (43.6206, -51) to (44.2206, -51.6)
  arc A9 centre (38.8206, 51.6) radius 0.6 clockwise from (38.8206, 51) to (38.2206, 51.6)
  arc A10 centre (43.6206, 51.6) radius 0.6 clockwise from (44.2206, 51.6) to (43.6206, 51)
  arc A11 centre (-38.8206, 51.6) radius 0.6 clockwise from (-38.2206, 51.6) to (-38.8206, 51)
  arc A12 centre (-43.6206, 51.6) radius 0.6 clockwise from (-43.6206, 51) to (-44.2206, 51.6)
  point P103 (-38.2206, -50)
  point P102 (-38.2206, -52.95)
  point P122 (38.2206, 52.95)
  perpendicular L85 L86
  parallel L85 L87
  parallel L86 L88
  coincident L2 P103
  perpendicular L2 L85
  coincident L80 P102
  coincident L74 P102
  perpendicular L97 L98
  parallel L97 L99
  parallel L98 L100
  perpendicular L54 L97
  coincident L92 P122
  coincident L76 P122
extrude "Extrude47" sketch "Sketch21" profile of L2 L18 L32 L74 L80 L81 L85 L86 L87 L88 blind -3
mirror "Mirror5" mirrorStitchTolerance 0.1
combine "Combine8"
offset_faces "OffsetFaces25" distance -0.5
offset_faces "OffsetFaces26" distance -0.5
move "Move3" TranslateX 0 TranslateY 0 TranslateZ 2.1
combine "Combine9"
combine "Combine11"
offset_faces "OffsetFaces27" distance 6
sketch "Sketch27" plane through (0, 0, -3.3) normal (0, 0, -1) x axis (1, 0, 0)
  line L1 (-13.5, 18) -> (13.5, 18)
  line L2 (-13.5, 50) -> (-13.5, 18)
  line L3 (-20.5, 50) -> (-13.5, 50)
  line L4 (-20.5, 18) -> (-20.5, 50)
  line L5 (-48, 18) -> (-20.5, 18)
  line L6 (-50, 20) -> (-48, 18)
  line L7 (-50, 48) -> (-50, 20)
  line L8 (-48, 50) -> (-50, 48)
  line L9 (-37.7206, 50) -> (-48, 50)
  line L10 (-37.7206, 52.95) -> (-37.7206, 50)
  line L11 (-44.75, 52.95) -> (-37.7206, 52.95)
  line L12 (-52.95, -44.75) -> (-52.95, 44.75)
  line L13 (-37.7206, -52.95) -> (-44.75, -52.95)
  line L14 (-37.7206, -50) -> (-37.7206, -52.95)
  line L15 (-48, -50) -> (-37.7206, -50)
  line L16 (-50, -48) -> (-48, -50)
  line L17 (-50, -20) -> (-50, -48)
  line L18 (-48, -18) -> (-50, -20)
  line L19 (-20.5, -18) -> (-48, -18)
  line L20 (-20.5, -50) -> (-20.5, -18)
  line L21 (-13.5, -50) -> (-20.5, -50)
  line L22 (-13.5, -18) -> (-13.5, -50)
  line L23 (13.5, -18) -> (-13.5, -18)
  line L24 (13.5, -50) -> (13.5, -18)
  line L25 (20.5, -50) -> (13.5, -50)
  line L26 (20.5, -18) -> (20.5, -50)
  line L27 (48, -18) -> (20.5, -18)
  line L28 (50, -20) -> (48, -18)
  line L29 (50, -48) -> (50, -20)
  line L30 (48, -50) -> (50, -48)
  line L31 (37.7206, -50) -> (48, -50)
  line L32 (37.7206, -52.95) -> (37.7206, -50)
  line L33 (44.75, -52.95) -> (37.7206, -52.95)
  line L34 (52.95, 44.75) -> (52.95, -44.75)
  line L35 (37.7206, 52.95) -> (44.75, 52.95)
  line L36 (37.7206, 50) -> (37.7206, 52.95)
  line L37 (48, 50) -> (37.7206, 50)
  line L38 (50, 48) -> (48, 50)
  line L39 (50, 20) -> (50, 48)
  line L40 (48, 18) -> (50, 20)
  line L41 (20.5, 18) -> (48, 18)
  line L42 (20.5, 50) -> (20.5, 18)
  line L43 (13.5, 50) -> (20.5, 50)
  line L44 (13.5, 18) -> (13.5, 50)
  line L45 (-48, -16) -> (-20.5, -16)
  line L46 (-50, -14) -> (-48, -16)
  line L47 (-50, 14) -> (-50, -14)
  line L48 (-48, 16) -> (-50, 14)
  line L49 (-20.5, 16) -> (-48, 16)
  line L50 (-20.5, -16) -> (-20.5, 16)
  line L51 (-13.5, -16) -> (13.5, -16)
  line L52 (-13.5, 16) -> (-13.5, -16)
  line L53 (13.5, 16) -> (-13.5, 16)
  line L54 (13.5, -16) -> (13.5, 16)
  line L55 (20.5, -16) -> (48, -16)
  line L56 (20.5, 16) -> (20.5, -16)
  line L57 (48, 16) -> (20.5, 16)
  line L58 (50, 14) -> (48, 16)
  line L59 (50, -14) -> (50, 14)
  line L60 (48, -16) -> (50, -14)
  line L61 (16.34, 32.54) -> (-16.68, 32.54)
  line L62 (-28.1693, 29.64) -> (27.8293, 29.64)
  line L63 (-28.1693, 35.44) -> (-28.1693, 29.64)
  line L64 (27.8293, 35.44) -> (-28.1693, 35.44)
  line L65 (27.8293, 29.64) -> (27.8293, 35.44)
  line L66 (-28.1693, 35.44) -> (27.8293, 29.64)
  line L67 (27.8293, 35.44) -> (-28.1693, 29.64)
  line L68 (-27.0118, -29.965) -> (-6.3482, -29.965)
  line L69 (-27.0118, -35.765) -> (-27.0118, -29.965)
  line L70 (-6.3482, -35.765) -> (-27.0118, -35.765)
  line L71 (-6.3482, -29.965) -> (-6.3482, -35.765)
  line L72 (-27.0118, -35.765) -> (-6.3482, -29.965)
  line L73 (-6.3482, -35.765) -> (-27.0118, -29.965)
  line L74 (6.7807, -30.6) -> (25.8793, -30.6)
  line L75 (6.7807, -36.4) -> (6.7807, -30.6)
  line L76 (25.8793, -36.4) -> (6.7807, -36.4)
  line L77 (25.8793, -30.6) -> (25.8793, -36.4)
  line L78 (6.7807, -36.4) -> (25.8793, -30.6)
  line L79 (25.8793, -36.4) -> (6.7807, -30.6)
  arc A1 centre (-44.75, 44.75) radius 8.2 clockwise from (-52.95, 44.75) to (-44.75, 52.95)
  arc A2 centre (-44.75, -44.75) radius 8.2 clockwise from (-44.75, -52.95) to (-52.95, -44.75)
  arc A3 centre (44.75, -44.75) radius 8.2 clockwise from (52.95, -44.75) to (44.75, -52.95)
  arc A4 centre (44.75, 44.75) radius 8.2 clockwise from (44.75, 52.95) to (52.95, 44.75)
  circle C1 centre (-16.68, -32.865) radius 2.675
  circle C2 centre (-16.68, 32.54) radius 2.675
  circle C3 centre (16.33, -33.5) radius 2.675
  circle C4 centre (16.34, 32.54) radius 2.675
  point P55 (-16.68, 32.54)
  point P74 (-16.68, 32.54)
  point P73 (16.34, 32.54)
  point P75 (16.34, 32.54)
  point P80 (-0.17, 32.54)
  point P85 (-16.68, -32.865)
  point P54 (-16.68, -32.865)
  point P90 (16.33, -33.5)
  point P72 (16.33, -33.5)
  point P77 (-28.1693, 29.64)
  point P78 (-28.1693, 35.44)
  point P82 (-27.0118, -29.965)
  point P83 (-27.0118, -35.765)
  point P87 (6.7807, -30.6)
  point P88 (6.7807, -36.4)
  coincident P55 P74
  coincident P73 P75
  horizontal L62
  perpendicular L62 L63
  parallel L62 L64
  parallel L63 L65
  coincident L66 P80
  coincident L67 P80
  midpoint L61 P80
  horizontal L68
  perpendicular L68 L69
  parallel L68 L70
  parallel L69 L71
  coincident L72 P85
  coincident L73 P85
  coincident P54 P85
  horizontal L74
  perpendicular L74 L75
  parallel L74 L76
  parallel L75 L77
  coincident L78 P90
  coincident L79 P90
  coincident P72 P90
  dimension "d418" distance P77 P78 = 5.8
  dimension "d419" distance P82 P83 = 5.8
  dimension "d420" distance P87 P88 = 5.8
extrude "Extrude50" cut sketch "Sketch27" profile of L20 L22 L24 L26 C1 C3 L68 L69 L70 L71 L74 L75 L76 L77 against normal blind 3.5
extrude "Extrude51" cut sketch "Sketch27" profile of L2 L4 L42 L44 C2 C4 L61 L62 L63 L64 L65 against normal blind 3.5
offset_faces "OffsetFaces28" distance 0.8
offset_faces "OffsetFaces29" distance 0.1
offset_faces "OffsetFaces30" distance 0.1
offset_faces "OffsetFaces31" distance 0.1
offset_faces "OffsetFaces32" distance 0.1
offset_faces "OffsetFaces33" distance 0.5
offset_faces "OffsetFaces34" distance 0.5
box_primitive "BoxPrimitive4" DistanceX 69.191 DistanceY 137.158 DistanceZ -30 OffsetDistanceX 0 OffsetDistanceY 0
extrude "Extrude48" sketch "Sketch18" profile of C4 C10 blind 3.5
extrude "Extrude49" sketch "Sketch18" profile of C1 C3 blind 3.5
box_primitive "BoxPrimitive3" DistanceX 172.726 DistanceY 191.806 DistanceZ -18 OffsetDistanceX 0 OffsetDistanceY 0 bodies "notch (1) (1)", "notch (1) (2)", "notch (1) (3)", "notch (1) (4)"
box_primitive "BoxPrimitive2" DistanceX 60 DistanceY 125 DistanceZ -25 OffsetDistanceX 0 OffsetDistanceY 0
box_primitive "BoxPrimitive1" DistanceX 180 DistanceY 190 DistanceZ -18 OffsetDistanceX 0 OffsetDistanceY 0
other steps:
derived_base_feature "Derived Base Feature"
create_component "CreateComponent1"
joint_origin "JointOrigin1"
named bodies: "Body", "close", "pcbholdup", "keyplate", "upmount3", "upmount1", "upmount4", "upmount2", "dwnmount4", "dwnmount2", "dwnmount1", "dwnmount4 (1)", "kwyplateheight", "close (1)", "close (2)", "close (3)", "pcbholdup (1)", "pcbholdup (2)", "pcbholdup (1) (1)", "notch (3)", "notch (2)", "notch", "notch (1)", "notch (1) (1)", "notch (1) (2)", "notch (1) (3)", "notch (1) (4)"

design "PCB_forkeypad"
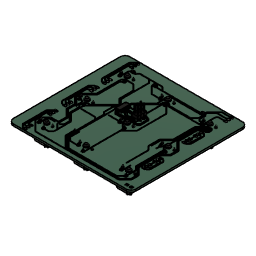
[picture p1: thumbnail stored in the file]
description: KiCad electronic assembly
part number: PCB_forkeypad1 1
description: Part Number
part number: PCB_forkeypad1 1.1.1
part number: PCB_forkeypad1 1.1.2
part number: Header_SMD_01x03_P2.54mm_Horizontal_Male
part number: PinHeader_2x03_P2.54mm_Vertical_SMD
part number: D_SOD-123
part number: Leads_Right
part number: Leads
part number: Package
part number: Dot
base_feature "Base Feature1"
base_feature "Base Feature1"
base_feature "Base Feature1"
base_feature "Base Feature1"
base_feature "Base Feature1"
base_feature "Base Feature1"
base_feature "Base Feature1"
base_feature "Base Feature1"
base_feature "Base Feature1"
base_feature "Base Feature1"
base_feature "Base Feature1"
remove_instance "RemoveInstance1"
copy_paste "CutPaste1"
copy_paste "CutPaste2"
copy_paste "CutPaste3"
copy_paste "CutPaste4"
copy_paste "CutPaste5"
copy_paste "CutPaste6"
copy_paste "CutPaste7"
copy_paste "CutPaste8"
copy_paste "CutPaste9"
copy_paste "CutPaste10"
copy_paste "CutPaste11"
copy_paste "CutPaste12"
copy_paste "CutPaste13"
copy_paste "CutPaste14"
copy_paste "CutPaste15"
copy_paste "CutPaste16"
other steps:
create_component "CreateComponent1"
create_component "CreateComponent1"
create_component "CreateComponent2"
create_component "CreateComponent2"
create_component "CreateComponent3"
create_component "CreateComponent4"
create_component "CreateComponent1"
create_component "CreateComponent1"
create_component "CreateComponent2"
create_component "CreateComponent3"
create_component "CreateComponent5"
create_component "CreateComponent6"
create_component "CreateComponent7"
create_component "CreateComponent8"
remove_instance "RemoveInstance2"
remove_instance "RemoveInstance3"
remove_instance "RemoveInstance4"
remove_instance "RemoveInstance5"
remove_instance "RemoveInstance6"
remove_instance "RemoveInstance7"
remove_instance "RemoveInstance8"
remove_instance "RemoveInstance9"
remove_instance "RemoveInstance10"
remove_instance "RemoveInstance11"
remove_instance "RemoveInstance12"
remove_instance "RemoveInstance13"
remove_instance "RemoveInstance14"
remove_instance "RemoveInstance15"
remove_instance "RemoveInstance16"
remove_instance "RemoveInstance17"

design "mockup_design2"
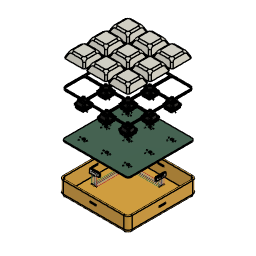
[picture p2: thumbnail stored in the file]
description: KiCad electronic assembly
part number: PCB_forkeypad1 1
description: Part Number
part number: D_SOD-123
part number: PCB_forkeypad1_pad
part number: PCB_forkeypad1_PCB
part number: COM-13834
